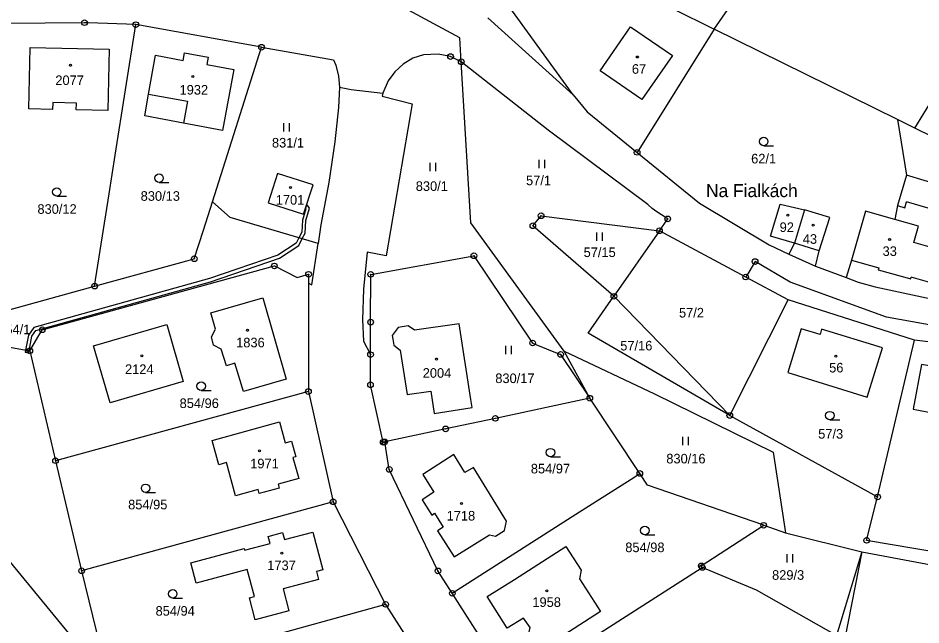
# Model space of a CAD drawing. Extents: x -680203 to -673936, y -1102717 to -1093650.
# Drawn here: x -679000.6 to -678840.6, y -1097626.7 to -1097519.2 of the extents above; entities that cross this region are included whole.
import ezdxf

# ---------------------------------------------------------------- set-up
doc = ezdxf.new("R2010")
doc.units = 0
for name, color, linetype in [('SOxx02xx_Koleje_param další_Popis10', 7, 'Continuous'), ('SOxx02xx_Staničení_Popis10', 7, 'Continuous'), ('SOxxxxxx_Koleje_hlavní_body_Popis10', 7, 'Continuous'), ('SOxxxxxx_Koleje_LN_parametry_Popis10', 7, 'Continuous'), ('SOxxxxxx_Koleje_param další_Popis10', 7, 'Continuous'), ('SOxxxxxx_Osa_bod_P', 7, 'Continuous'), ('SOxxxxxx_Staničení_Popis10', 7, 'Continuous'), ('x_prac', 7, 'Continuous')]:
    doc.layers.add(name, color=color, linetype=linetype)

msp = doc.modelspace()

# ---------------------------------------------------------------- linework, layer by layer
at = {"layer": 'SOxx02xx_Koleje_param další_Popis10'}
for centre, radius in [((-678988.8, -1097519.98), 0.5), ((-678988.8, -1097519.98), 0.0303), ((-678979.71, -1097520.32), 0.5), ((-678979.71, -1097520.32), 0.0303), ((-678957.43, -1097524.33), 0.5), ((-678957.43, -1097524.33), 0.0303), ((-678923.94, -1097525.98), 0.5), ((-678923.94, -1097525.98), 0.0303), ((-678922.04, -1097526.91), 0.5), ((-678922.04, -1097526.91), 0.5), ((-678922.04, -1097526.91), 0.0303), ((-678922.04, -1097526.91), 0.0303), ((-678890.88, -1097542.96), 0.5), ((-678890.88, -1097542.96), 0.0303), ((-678907.9, -1097554.19), 0.5), ((-678907.9, -1097554.19), 0.0303), ((-678885.46, -1097554.74), 0.5), ((-678885.46, -1097554.74), 0.0303), ((-678909.36, -1097555.96), 0.5), ((-678909.36, -1097555.96), 0.0303), ((-678886.93, -1097556.86), 0.5), ((-678886.93, -1097556.86), 0.0303), ((-678969.34, -1097561.81), 0.5), ((-678919.8, -1097561.28), 0.5), ((-678919.8, -1097561.28), 0.0303), ((-678969.34, -1097561.81), 0.0303), ((-678955.15, -1097563.09), 0.5), ((-678869.98, -1097562.3), 0.5), ((-678869.98, -1097562.3), 0.0303), ((-678955.15, -1097563.09), 0.0303), ((-678949.09, -1097564.56), 0.5), ((-678949.09, -1097564.56), 0.0303), ((-678938.09, -1097564.58), 0.5), ((-678938.09, -1097564.58), 0.0303), ((-678871.65, -1097565.05), 0.5), ((-678871.65, -1097565.05), 0.0303), ((-678987, -1097566.67), 0.5), ((-678987, -1097566.67), 0.0303), ((-678895, -1097568.46), 0.5), ((-678895, -1097568.46), 0.0303), ((-678996.27, -1097574.4), 0.5), ((-678938.1, -1097573.04), 0.5), ((-678938.1, -1097573.04), 0.0303), ((-678996.27, -1097574.4), 0.0303), ((-678909.4, -1097576.74), 0.5), ((-678909.4, -1097576.74), 0.0303), ((-678998.49, -1097578.13), 0.5), ((-678998.49, -1097578.13), 0.0303), ((-678938.11, -1097578.8), 0.5), ((-678938.11, -1097578.8), 0.0303), ((-678904.43, -1097578.76), 0.5), ((-678904.43, -1097578.76), 0.0303), ((-678938.12, -1097584.14), 0.5), ((-678949.12, -1097585.35), 0.5), ((-678949.12, -1097585.35), 0.0303), ((-678938.12, -1097584.14), 0.0303), ((-678899.26, -1097586.53), 0.5), ((-678899.26, -1097586.53), 0.0303), ((-678916, -1097590.09), 0.5), ((-678916, -1097590.09), 0.0303), ((-678874.46, -1097589.59), 0.5), ((-678874.46, -1097589.59), 0.0303), ((-678924.8, -1097591.96), 0.5), ((-678924.8, -1097591.96), 0.0303), ((-678935.86, -1097594.32), 0.5), ((-678935.6, -1097594.26), 0.5), ((-678935.86, -1097594.32), 0.0303), ((-678935.6, -1097594.26), 0.0303), ((-678993.93, -1097597.6), 0.5), ((-678993.93, -1097597.6), 0.0303), ((-678934.79, -1097599.14), 0.5), ((-678934.79, -1097599.14), 0.0303), ((-678890.4, -1097599.86), 0.5), ((-678890.4, -1097599.86), 0.0303), ((-678944.74, -1097604.87), 0.5), ((-678848.27, -1097604.02), 0.5), ((-678848.27, -1097604.02), 0.0303), ((-678944.74, -1097604.87), 0.0303), ((-678868.46, -1097609.04), 0.5), ((-678868.46, -1097609.04), 0.0303), ((-678850.22, -1097611.71), 0.5), ((-678850.22, -1097611.71), 0.0303), ((-678989.3, -1097617.1), 0.5), ((-678989.3, -1097617.1), 0.0303), ((-678926.17, -1097617.13), 0.5), ((-678926.17, -1097617.13), 0.0303), ((-678879.51, -1097616.24), 0.5), ((-678879.33, -1097616.51), 0.5), ((-678879.51, -1097616.24), 0.0303), ((-678879.33, -1097616.51), 0.0303), ((-678923.63, -1097621.1), 0.5), ((-678923.63, -1097621.1), 0.0303), ((-678935.44, -1097623.06), 0.5), ((-678935.44, -1097623.06), 0.0303)]:
    msp.add_circle(centre, radius, dxfattribs=at)
at = {"layer": 'SOxxxxxx_Koleje_hlavní_body_Popis10'}
for p, q in [((-678953.45, -1097539.27), (-678953.45, -1097537.77)), ((-678952.45, -1097539.27), (-678952.45, -1097537.77)), ((-678868.46, -1097541.79), (-678866.71, -1097541.79)), ((-678927.54, -1097546.3), (-678927.54, -1097544.8)), ((-678926.54, -1097546.3), (-678926.54, -1097544.8)), ((-678908.23, -1097545.78), (-678908.23, -1097544.28)), ((-678907.23, -1097545.78), (-678907.23, -1097544.28)), ((-678975.58, -1097548.28), (-678973.83, -1097548.28)), ((-678993.72, -1097550.73), (-678991.97, -1097550.73)), ((-678898, -1097558.64), (-678898, -1097557.14)), ((-678897, -1097558.64), (-678897, -1097557.14)), ((-678914.16, -1097578.73), (-678914.16, -1097577.23)), ((-678913.16, -1097578.73), (-678913.16, -1097577.23)), ((-678968.12, -1097585.14), (-678966.37, -1097585.14)), ((-678856.74, -1097590.36), (-678854.99, -1097590.36)), ((-678882.76, -1097594.84), (-678882.76, -1097593.34)), ((-678881.76, -1097594.84), (-678881.76, -1097593.34)), ((-678906.23, -1097596.91), (-678904.48, -1097596.91)), ((-678977.96, -1097603.23), (-678976.21, -1097603.23)), ((-678889.52, -1097610.72), (-678887.77, -1097610.72)), ((-678864.29, -1097615.65), (-678864.29, -1097614.15)), ((-678863.29, -1097615.65), (-678863.29, -1097614.15)), ((-678973.16, -1097621.94), (-678971.41, -1097621.94))]:
    msp.add_line(p, q, dxfattribs=at)
for centre in [(-678868.46, -1097541.04), (-678975.58, -1097547.53), (-678993.72, -1097549.98), (-678968.12, -1097584.39), (-678856.74, -1097589.61), (-678906.23, -1097596.16), (-678977.96, -1097602.48), (-678889.52, -1097609.97), (-678973.16, -1097621.19)]:
    msp.add_circle(centre, 0.75, dxfattribs=at)
at = {"layer": 'SOxxxxxx_Koleje_LN_parametry_Popis10'}
for points in [[(-678998.15, -1097575.55), (-678997.42, -1097574.51), (-678966.44, -1097565.88), (-678954.26, -1097561.71), (-678950.84, -1097559.44), (-678950.2, -1097558.25), (-678949.67, -1097557.28), (-678949.56, -1097555.05), (-678948.92, -1097552.82), (-678949.42, -1097552.17), (-678949.64, -1097552.86), (-678949.58, -1097552.94), (-678950.16, -1097554.95), (-678950.27, -1097557.12), (-678950.79, -1097558.08), (-678951.3, -1097559.02), (-678954.52, -1097561.17), (-678966.62, -1097565.3), (-678997.78, -1097573.99), (-678998.73, -1097575.33), (-678999.26, -1097577.99), (-678998.62, -1097578.11)], [(-678999.26, -1097577.99), (-678999.33, -1097578.39), (-678998.69, -1097578.5), (-678998.62, -1097578.11)]]:
    msp.add_lwpolyline(points, close=True, dxfattribs=at)
at = {"layer": 'SOxxxxxx_Koleje_param další_Popis10'}
for centre in [(-678890.84, -1097526.06), (-678991.25, -1097527.53), (-678969.61, -1097529.5), (-678952.3, -1097549.2), (-678864.19, -1097554.1), (-678859.69, -1097555.86), (-678846.14, -1097558.38), (-678959.91, -1097574.49), (-678978.65, -1097579), (-678855.67, -1097579.08), (-678926.44, -1097579.58), (-678957.81, -1097595.87), (-678922.01, -1097605.17), (-678953.84, -1097613.99), (-678906.89, -1097620.68)]:
    msp.add_circle(centre, 0.175, dxfattribs=at)
at = {"layer": 'SOxxxxxx_Staničení_Popis10'}
for p, q in [((-678977.44, -1097532.65), (-678970.55, -1097533.9)), ((-678970.55, -1097533.9), (-678971.24, -1097537.81)), ((-678832.48, -1097550.2), (-678843.15, -1097547.02)), ((-678843.46, -1097552.76), (-678843.16, -1097551.73)), ((-678833.72, -1097554.5), (-678843.16, -1097551.73)), ((-678844.72, -1097552.39), (-678843.46, -1097552.76)), ((-678841.01, -1097556.05), (-678845.23, -1097554.85)), ((-678841.84, -1097558.95), (-678841.01, -1097556.05)), ((-678858.62, -1097560.38), (-678862.98, -1097559.07)), ((-678835.58, -1097560.73), (-678841.84, -1097558.95)), ((-678852.92, -1097562.05), (-678848.06, -1097563.44)), ((-678848.06, -1097563.44), (-678848.15, -1097563.75)), ((-678848.15, -1097563.75), (-678842.41, -1097565.39)), ((-678842.41, -1097565.39), (-678842.33, -1097565.09)), ((-678837.36, -1097566.51), (-678842.33, -1097565.09))]:
    msp.add_line(p, q, dxfattribs=at)
at = {"layer": 'x_prac'}
for p, q in [((-678877.23, -1097521.11), (-678859.39, -1097495.31)), ((-678841.69, -1097538.65), (-678818.57, -1097500.83)), ((-678902.19, -1097532.76), (-678913.72, -1097516.9)), ((-678917.34, -1097519.1), (-678902.19, -1097532.76)), ((-678957.43, -1097524.33), (-678979.71, -1097520.32)), ((-678877.23, -1097521.11), (-678890.88, -1097542.96)), ((-678844.72, -1097537.16), (-678877.23, -1097521.11)), ((-678966.14, -1097551.74), (-678957.43, -1097524.33)), ((-678920.34, -1097555.47), (-678922.04, -1097526.91)), ((-678906.62, -1097539.03), (-678922.04, -1097526.91)), ((-678920.34, -1097555.47), (-678922.04, -1097526.91)), ((-678902.19, -1097532.76), (-678899.72, -1097535.75)), ((-678899.72, -1097535.75), (-678890.88, -1097542.96)), ((-678841.69, -1097538.65), (-678844.72, -1097537.16)), ((-678861.2, -1097553.16), (-678862.98, -1097559.07)), ((-678903.83, -1097578.18), (-678920.34, -1097555.47)), ((-678903.83, -1097578.18), (-678920.34, -1097555.47)), ((-678886.93, -1097556.86), (-678895, -1097568.46)), ((-678871.65, -1097565.05), (-678886.93, -1097556.86)), ((-678862.98, -1097559.07), (-678864.01, -1097561)), ((-678864.01, -1097561), (-678859.25, -1097563.12)), ((-678859.25, -1097563.12), (-678853.82, -1097565.16)), ((-678949.09, -1097566.14), (-678949.12, -1097585.35)), ((-678864.11, -1097569.09), (-678871.65, -1097565.05)), ((-679003.45, -1097571.2), (-678987, -1097566.67)), ((-678895, -1097568.46), (-678874.46, -1097589.59)), ((-678874.46, -1097589.59), (-678864.11, -1097569.09)), ((-678841.73, -1097576.24), (-678864.11, -1097569.09)), ((-678848.27, -1097604.02), (-678841.73, -1097576.24)), ((-678822.82, -1097578.47), (-678841.73, -1097576.24)), ((-678998.49, -1097578.13), (-678993.93, -1097597.6)), ((-678899.26, -1097586.53), (-678903.83, -1097578.18)), ((-678949.12, -1097585.35), (-678993.93, -1097597.6)), ((-678949.12, -1097585.35), (-678944.74, -1097604.87)), ((-678890.4, -1097599.86), (-678899.26, -1097586.53)), ((-678874.46, -1097589.59), (-678848.27, -1097604.02)), ((-678993.93, -1097597.6), (-678989.3, -1097617.1)), ((-678889.04, -1097601.92), (-678890.4, -1097599.86)), ((-678868.46, -1097609.04), (-678889.04, -1097601.92)), ((-678944.74, -1097604.87), (-678989.3, -1097617.1)), ((-678944.74, -1097604.87), (-678935.44, -1097623.06)), ((-678879.51, -1097616.24), (-678868.46, -1097609.04)), ((-678868.46, -1097609.04), (-678864.59, -1097610.38)), ((-678864.59, -1097610.38), (-678851.08, -1097613.73)), ((-678864.59, -1097610.38), (-678851.08, -1097613.73)), ((-678984.53, -1097636.69), (-679003.26, -1097613.93)), ((-678851.08, -1097613.73), (-678855.57, -1097628.56)), ((-678851.08, -1097613.73), (-678828.6, -1097617.98)), ((-678851.08, -1097613.73), (-678828.6, -1097617.98)), ((-678989.3, -1097617.1), (-678984.53, -1097636.69)), ((-678912.86, -1097637.95), (-678879.33, -1097616.51)), ((-678879.33, -1097616.51), (-678879.51, -1097616.24)), ((-678912.86, -1097637.95), (-678923.63, -1097621.1)), ((-678935.44, -1097623.06), (-678959.4, -1097629.72))]:
    msp.add_line(p, q, dxfattribs=at)
for points in [[(-678913.72, -1097516.9), (-678898.89, -1097503.51), (-678884.62, -1097517.47), (-678877.23, -1097521.11)], [(-678922.04, -1097526.91), (-678922.29, -1097522.64), (-678936.02, -1097515.23), (-678948.18, -1097510.32), (-678948.85, -1097509.43)], [(-678922.04, -1097526.91), (-678922.29, -1097522.64), (-678936.02, -1097515.23), (-678948.18, -1097510.32), (-678948.85, -1097509.43)], [(-678979.71, -1097520.32), (-678988.1, -1097520), (-678988.8, -1097519.98), (-679002.71, -1097520.1)], [(-678987, -1097566.67), (-678984.43, -1097550.29), (-678983.35, -1097543.44), (-678979.71, -1097520.32)], [(-678890.02, -1097533.6), (-678897.45, -1097528.51), (-678892.04, -1097520.69), (-678884.63, -1097525.79), (-678890.02, -1097533.6)], [(-678990.23, -1097534.24), (-678994.43, -1097534.15), (-678994.46, -1097535.35), (-678998.65, -1097535.26), (-678998.41, -1097524.37), (-678984.42, -1097524.66), (-678984.65, -1097535.56), (-678990.25, -1097535.44), (-678990.23, -1097534.24)], [(-678957.43, -1097524.33), (-678944.66, -1097526.59), (-678944.26, -1097527.51), (-678943.79, -1097529.44), (-678943.61, -1097531.42)], [(-678971.24, -1097537.81), (-678978.09, -1097536.51), (-678977.44, -1097532.65), (-678976.19, -1097525.76), (-678971.29, -1097526.65), (-678971.05, -1097525.32), (-678966.89, -1097526.07), (-678967.14, -1097527.4), (-678962.36, -1097528.26), (-678964.35, -1097539.08), (-678971.24, -1097537.81)], [(-678926.15, -1097525.57), (-678928.72, -1097525.68), (-678930.62, -1097526.28), (-678932.32, -1097527.35), (-678933.78, -1097528.7), (-678934.97, -1097530.31), (-678935.91, -1097532.46)], [(-678922.04, -1097526.91), (-678923.94, -1097525.98), (-678926.15, -1097525.57)], [(-678943.61, -1097531.42), (-678943.78, -1097535.03), (-678944.45, -1097541.08), (-678945.51, -1097548.31), (-678946.92, -1097555.79), (-678947.41, -1097559.08)], [(-678943.61, -1097531.42), (-678941.52, -1097531.83), (-678935.91, -1097532.46)], [(-678935.91, -1097532.46), (-678936.07, -1097533.02), (-678930.75, -1097534.36), (-678935.35, -1097561.31), (-678938.72, -1097560.66), (-678939.38, -1097567.18), (-678939.52, -1097572.66), (-678939.36, -1097576.41), (-678938.11, -1097578.8)], [(-678844.72, -1097537.16), (-678843.15, -1097547.02), (-678844.72, -1097552.39), (-678845.23, -1097554.85), (-678850.44, -1097553.37), (-678852.92, -1097562.05), (-678853.82, -1097565.16)], [(-678828.87, -1097545.34), (-678828.82, -1097545), (-678841.69, -1097538.65)], [(-678886.93, -1097556.86), (-678885.46, -1097554.74), (-678886.54, -1097554), (-678887.41, -1097553.5), (-678888.23, -1097552.9), (-678888.98, -1097552.19), (-678906.62, -1097539.03)], [(-678890.88, -1097542.96), (-678879.82, -1097551.97), (-678867.5, -1097559.34), (-678864.01, -1097561)], [(-678954.61, -1097546.7), (-678956.28, -1097551.88), (-678949.98, -1097553.91)], [(-678949.98, -1097553.91), (-678948.3, -1097548.73), (-678954.61, -1097546.7)], [(-678987, -1097566.67), (-678969.34, -1097561.81), (-678967.73, -1097556.75), (-678966.14, -1097551.74)], [(-678947.41, -1097559.08), (-678962.96, -1097554.48), (-678966.14, -1097551.74)], [(-678862.98, -1097559.07), (-678867.23, -1097557.8), (-678865.56, -1097552.13), (-678861.2, -1097553.16)], [(-678859.25, -1097563.12), (-678858.62, -1097560.38), (-678856.76, -1097554.49), (-678861.2, -1097553.16)], [(-678895, -1097568.46), (-678909.36, -1097555.96), (-678907.9, -1097554.19), (-678886.93, -1097556.86)], [(-678949.09, -1097566.14), (-678948.5, -1097566.44), (-678947.41, -1097559.08)], [(-678938.11, -1097578.8), (-678938.1, -1097573.04), (-678938.09, -1097564.58), (-678919.8, -1097561.28), (-678909.4, -1097576.74), (-678904.43, -1097578.76), (-678899.26, -1097586.53)], [(-678780.66, -1097569.63), (-678794.4, -1097575.79), (-678824.67, -1097576.09), (-678846.71, -1097572.15), (-678863.75, -1097565.95), (-678869.98, -1097562.3), (-678871.65, -1097565.05)], [(-678998.49, -1097578.13), (-678996.27, -1097574.4), (-678955.15, -1097563.09), (-678951.12, -1097565.12), (-678949.09, -1097564.56), (-678949.09, -1097566.14)], [(-678853.82, -1097565.16), (-678851.69, -1097565.96), (-678848.7, -1097566.8), (-678837.96, -1097569.09), (-678832.4, -1097569.66)], [(-679035.87, -1097567.18), (-679012.05, -1097575.63), (-678998.49, -1097578.13)], [(-678960.61, -1097585.32), (-678962.14, -1097580.32), (-678963.65, -1097580.79), (-678964.56, -1097577.81), (-678965.94, -1097577.13), (-678966.29, -1097575.64), (-678965.57, -1097574.31), (-678966.39, -1097571.38), (-678957.21, -1097568.75), (-678953.07, -1097583.16), (-678960.61, -1097585.32)], [(-678874.46, -1097589.59), (-678899.54, -1097574.98), (-678895, -1097568.46)], [(-678984.24, -1097587.33), (-678987.18, -1097577.24), (-678974.2, -1097573.48), (-678971.29, -1097583.54), (-678984.24, -1097587.33)], [(-678933.23, -1097573.97), (-678934.28, -1097575.41), (-678934.17, -1097576.07), (-678933.99, -1097577.15), (-678932.84, -1097577.99), (-678931.65, -1097585.89), (-678927.43, -1097585.25), (-678926.82, -1097589.22), (-678920.13, -1097588.19), (-678920.36, -1097586.73), (-678922.42, -1097573.33), (-678930.33, -1097574.48), (-678931.45, -1097573.72), (-678933.23, -1097573.97)], [(-678858.48, -1097575.21), (-678861.79, -1097574.21), (-678864.19, -1097581.98), (-678850.11, -1097586.31), (-678847.43, -1097577.59), (-678858.21, -1097574.29), (-678858.48, -1097575.21)], [(-678935.6, -1097594.26), (-678935.86, -1097594.32), (-678938.12, -1097584.14), (-678938.11, -1097578.8)], [(-678903.83, -1097578.18), (-678887.82, -1097585.75), (-678866.79, -1097596.07), (-678864.59, -1097610.38)], [(-678903.83, -1097578.18), (-678887.82, -1097585.75), (-678866.79, -1097596.07), (-678864.59, -1097610.38)], [(-678840.48, -1097580.53), (-678841.99, -1097588.47), (-678827.36, -1097591.27), (-678825.64, -1097582.24), (-678836.74, -1097580.18), (-678836.92, -1097581.12), (-678840.48, -1097580.53)], [(-678899.26, -1097586.53), (-678916, -1097590.09), (-678924.8, -1097591.96), (-678935.6, -1097594.26)], [(-678962.01, -1097603.8), (-678963.63, -1097597.93), (-678965, -1097598.3), (-678966.19, -1097594), (-678954.27, -1097590.71), (-678953.23, -1097594.46), (-678952.09, -1097594.15), (-678951.33, -1097596.89), (-678951.86, -1097597.04), (-678950.84, -1097600.74), (-678954.48, -1097601.74), (-678954.28, -1097602.45), (-678957.85, -1097603.43), (-678958.05, -1097602.71), (-678962.01, -1097603.8)], [(-678923.63, -1097621.1), (-678926.17, -1097617.13), (-678934.79, -1097599.14), (-678935.6, -1097594.26)], [(-678926.26, -1097610.05), (-678923.28, -1097614.65), (-678917.02, -1097610.75), (-678915.99, -1097610.99), (-678914.39, -1097609.98), (-678914, -1097608.34), (-678919.87, -1097598.78), (-678921.38, -1097599.71), (-678923.36, -1097596.48), (-678928.87, -1097600.03), (-678926.87, -1097603.16), (-678928.97, -1097604.51), (-678927.26, -1097607.22), (-678926.76, -1097606.9), (-678925.24, -1097609.39), (-678926.26, -1097610.05)], [(-678923.63, -1097621.1), (-678901.73, -1097607.1), (-678891.96, -1097600.85), (-678890.4, -1097599.86)], [(-678830.25, -1097610.94), (-678832.75, -1097614.68), (-678850.22, -1097611.71), (-678848.27, -1097604.02)], [(-678953.59, -1097620.3), (-678952.58, -1097624.2), (-678958.55, -1097625.79), (-678959.55, -1097621.9), (-678958.7, -1097621.65), (-678959.96, -1097616.88), (-678968.99, -1097619.28), (-678969.98, -1097615.68), (-678960.52, -1097613.16), (-678960.44, -1097613.47), (-678955.91, -1097612.25), (-678956.25, -1097611.02), (-678953.7, -1097610.34), (-678953.34, -1097611.58), (-678948.31, -1097610.25), (-678946.54, -1097616.95), (-678947.68, -1097617.25), (-678947.31, -1097618.64), (-678953.59, -1097620.3)], [(-678909.32, -1097630.44), (-678910.26, -1097629), (-678909.86, -1097627.16), (-678911.01, -1097625.48), (-678913.91, -1097627.3), (-678917.47, -1097621.69), (-678912.61, -1097618.62), (-678903.51, -1097612.83), (-678900.79, -1097617.01), (-678901.11, -1097618.52), (-678897.39, -1097624.34), (-678907.53, -1097630.87), (-678909.32, -1097630.44)], [(-678851.08, -1097613.73), (-678854.07, -1097629.08), (-678858.58, -1097647.74)], [(-678855.57, -1097628.56), (-678869.73, -1097620.55), (-678879.33, -1097616.51)], [(-678935.44, -1097623.06), (-678919.47, -1097648.09), (-678920.39, -1097652.2), (-678938.09, -1097663.44)]]:
    msp.add_lwpolyline(points, dxfattribs=at)

# ---------------------------------------------------------------- texts
at = {"layer": 'SOxx02xx_Staničení_Popis10'}
msp.add_text('Na Fialkách', height=2.3, dxfattribs=at).set_placement((-678878.67, -1097550.89))
at = {"layer": 'SOxxxxxx_Osa_bod_P'}
for s, p in [('67', (-678891.81, -1097529.03)), ('2077', (-678993.96, -1097531.03)), ('1932', (-678971.95, -1097532.72)), ('831/1', (-678955.58, -1097542.1)), ('62/1', (-678870.68, -1097544.92)), ('830/1', (-678930.1, -1097549.79)), ('57/1', (-678910.56, -1097548.78)), ('830/13', (-678978.84, -1097551.54)), ('1701', (-678954.91, -1097552.23)), ('830/12', (-678997.13, -1097553.85)), ('92', (-678865.63, -1097557.07)), ('43', (-678861.53, -1097559.16)), ('57/15', (-678900.36, -1097561.51)), ('33', (-678847.39, -1097561.31)), ('57/2', (-678883.46, -1097572.22)), ('854/1', (-679004.07, -1097575.18)), ('1836', (-678961.92, -1097577.51)), ('57/16', (-678893.87, -1097578.06)), ('2124', (-678981.61, -1097582.23)), ('56', (-678856.86, -1097581.96)), ('2004', (-678928.87, -1097582.9)), ('830/17', (-678916.01, -1097583.84)), ('854/96', (-678971.94, -1097588.26)), ('57/3', (-678858.8, -1097593.69)), ('830/16', (-678885.71, -1097598.08)), ('1971', (-678959.43, -1097598.95)), ('854/97', (-678909.71, -1097599.85)), ('854/95', (-678981.06, -1097606.22)), ('1718', (-678924.63, -1097608.2)), ('854/98', (-678892.98, -1097613.8)), ('1737', (-678956.41, -1097616.99)), ('829/3', (-678866.97, -1097618.7)), ('1958', (-678909.44, -1097623.51)), ('854/94', (-678976.2, -1097625.06))]:
    msp.add_text(s, height=1.7, dxfattribs=at).set_placement(p)

doc.saveas('drawing.dxf')
